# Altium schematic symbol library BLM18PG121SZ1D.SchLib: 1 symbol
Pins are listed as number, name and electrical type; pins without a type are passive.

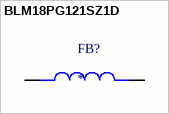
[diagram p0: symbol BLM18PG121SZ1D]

## BLM18PG121SZ1D
designator FB?
120 Ohms @ 100MHz 1 Power Line Ferrite Bead 0603 (1608 Metric) 2A 50mOhm; MP: BLM18PG121SZ1D; MF: Murata Electronics
footprint BEADC1608X95N
pins: 1, 2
